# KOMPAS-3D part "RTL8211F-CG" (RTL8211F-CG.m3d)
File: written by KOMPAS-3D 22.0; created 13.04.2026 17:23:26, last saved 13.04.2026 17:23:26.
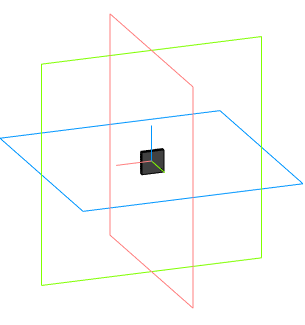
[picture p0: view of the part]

Document properties: Автор: Andrey; Полное имя файла: C:\Users\User1\Documents\RTL8211F-CG.m3d

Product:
- Part/product: RTL8211F-CG

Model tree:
1. Операция без истории:1
2. Операция без истории:2
3. Операция без истории:3
4. Операция без истории:4
5. Операция без истории:5
6. Операция без истории:6
7. Операция без истории:7
8. Операция без истории:8
9. Операция без истории:9
10. Операция без истории:10
11. Операция без истории:11
12. Операция без истории:12
13. Операция без истории:13
14. Операция без истории:14
15. Операция без истории:15
16. Операция без истории:16
17. Операция без истории:17
18. Операция без истории:18
19. Операция без истории:19
20. Операция без истории:20
21. Операция без истории:21
22. Операция без истории:22
23. Операция без истории:23
24. Операция без истории:24
25. Операция без истории:25
26. Операция без истории:26
27. Операция без истории:27
28. Операция без истории:28
29. Операция без истории:29
30. Операция без истории:30
31. Операция без истории:31
32. Операция без истории:32
33. Операция без истории:33
34. Операция без истории:34
35. Операция без истории:35
36. Операция без истории:36
37. Операция без истории:37
38. Операция без истории:38
39. Операция без истории:39
40. Операция без истории:40
41. Операция без истории:41
42. Операция без истории:42
43. Операция без истории:43
44. Операция без истории:44
45. Операция без истории:45
46. Операция без истории:46
47. Операция без истории:47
